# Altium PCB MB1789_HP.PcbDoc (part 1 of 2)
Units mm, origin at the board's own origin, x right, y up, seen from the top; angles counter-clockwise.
Board outline 60 x 34 mm, 4 copper layers (Top Layer, Mid-Layer 1, Mid-Layer 2, Bottom Layer), stack 1.07 mm thick; 66 components, 56 nets, 212 pads, 990 vias.
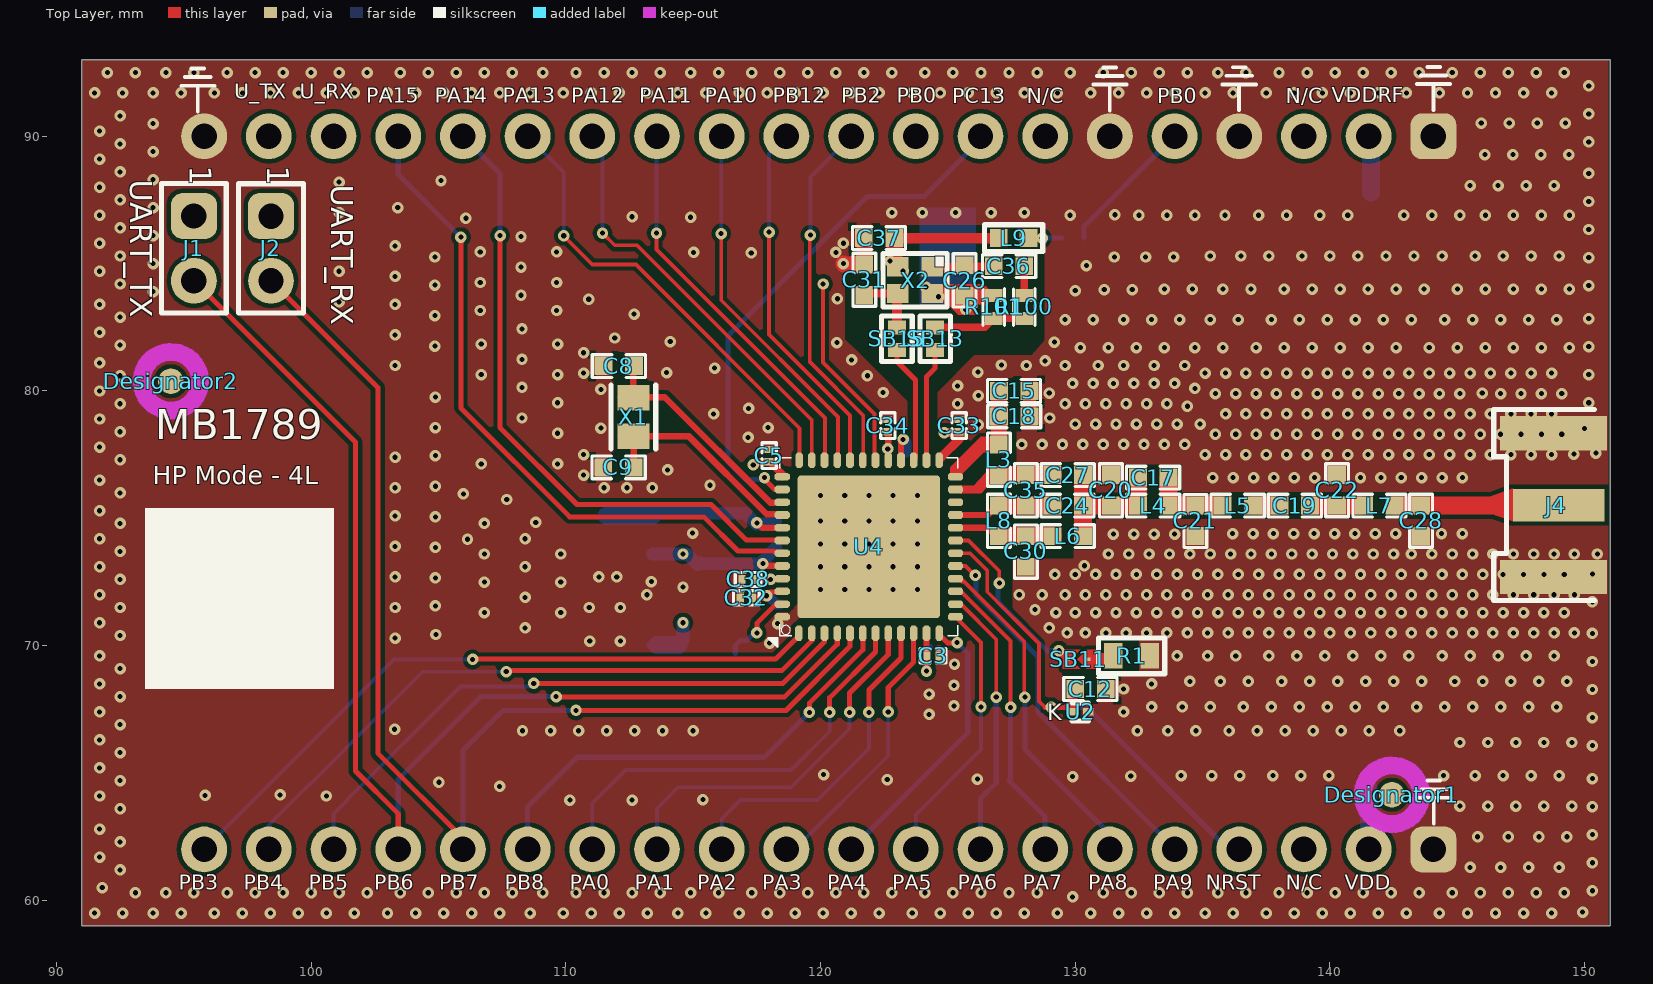
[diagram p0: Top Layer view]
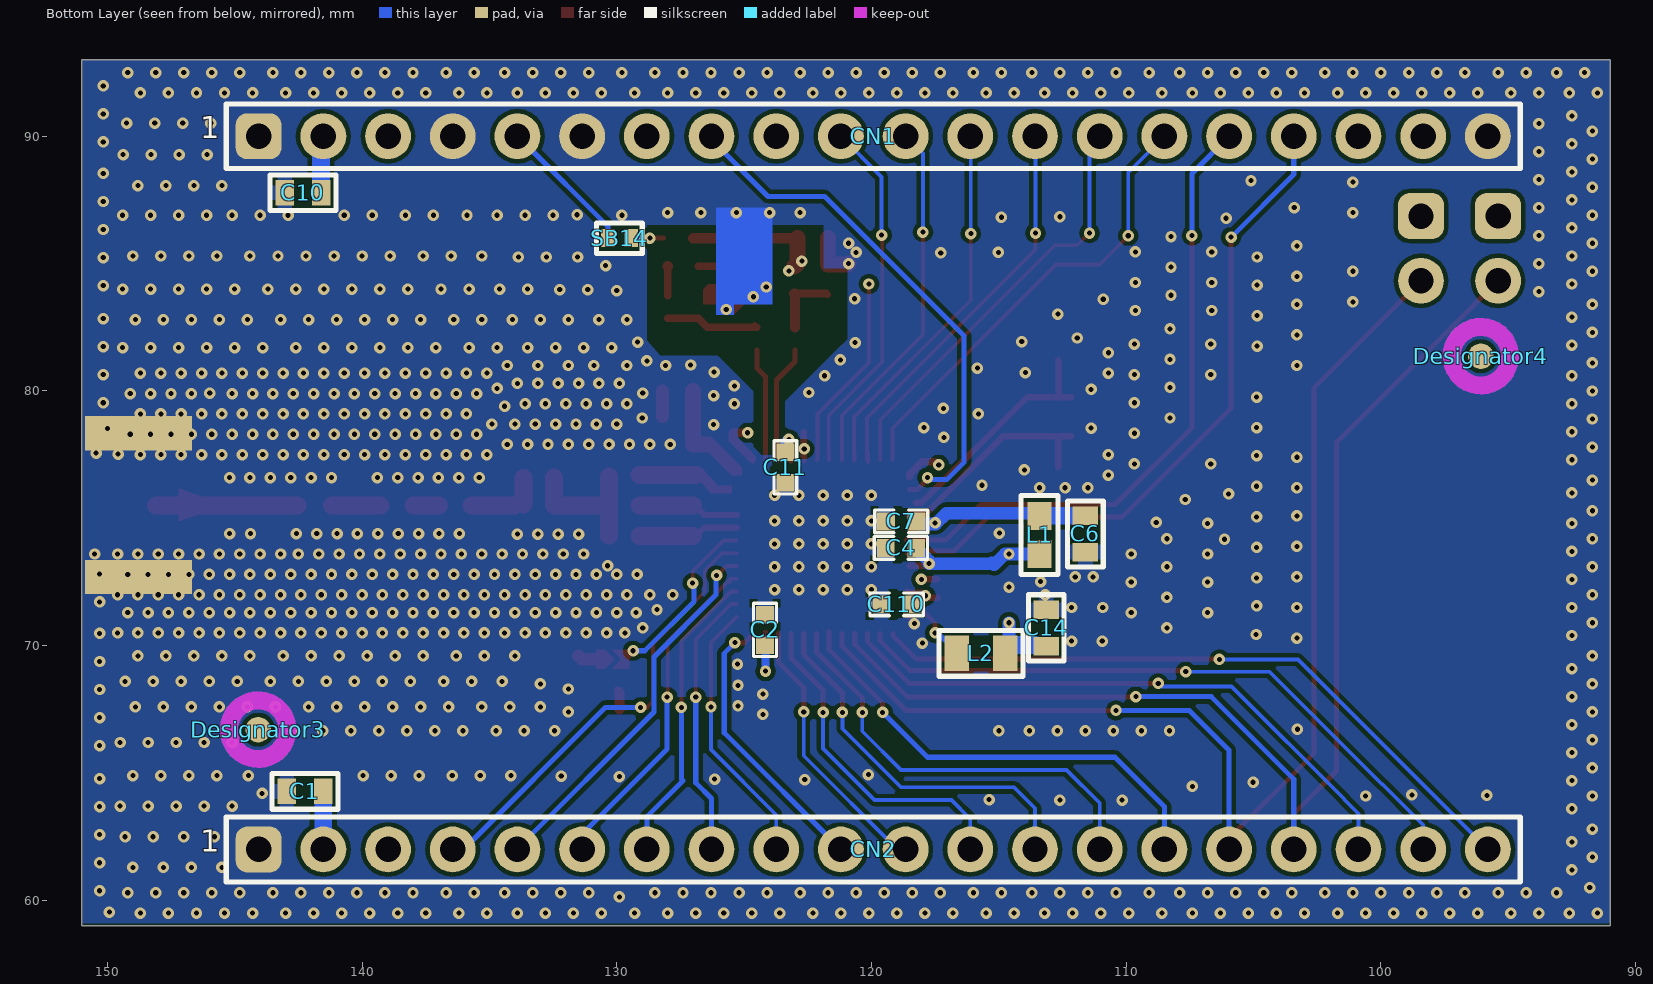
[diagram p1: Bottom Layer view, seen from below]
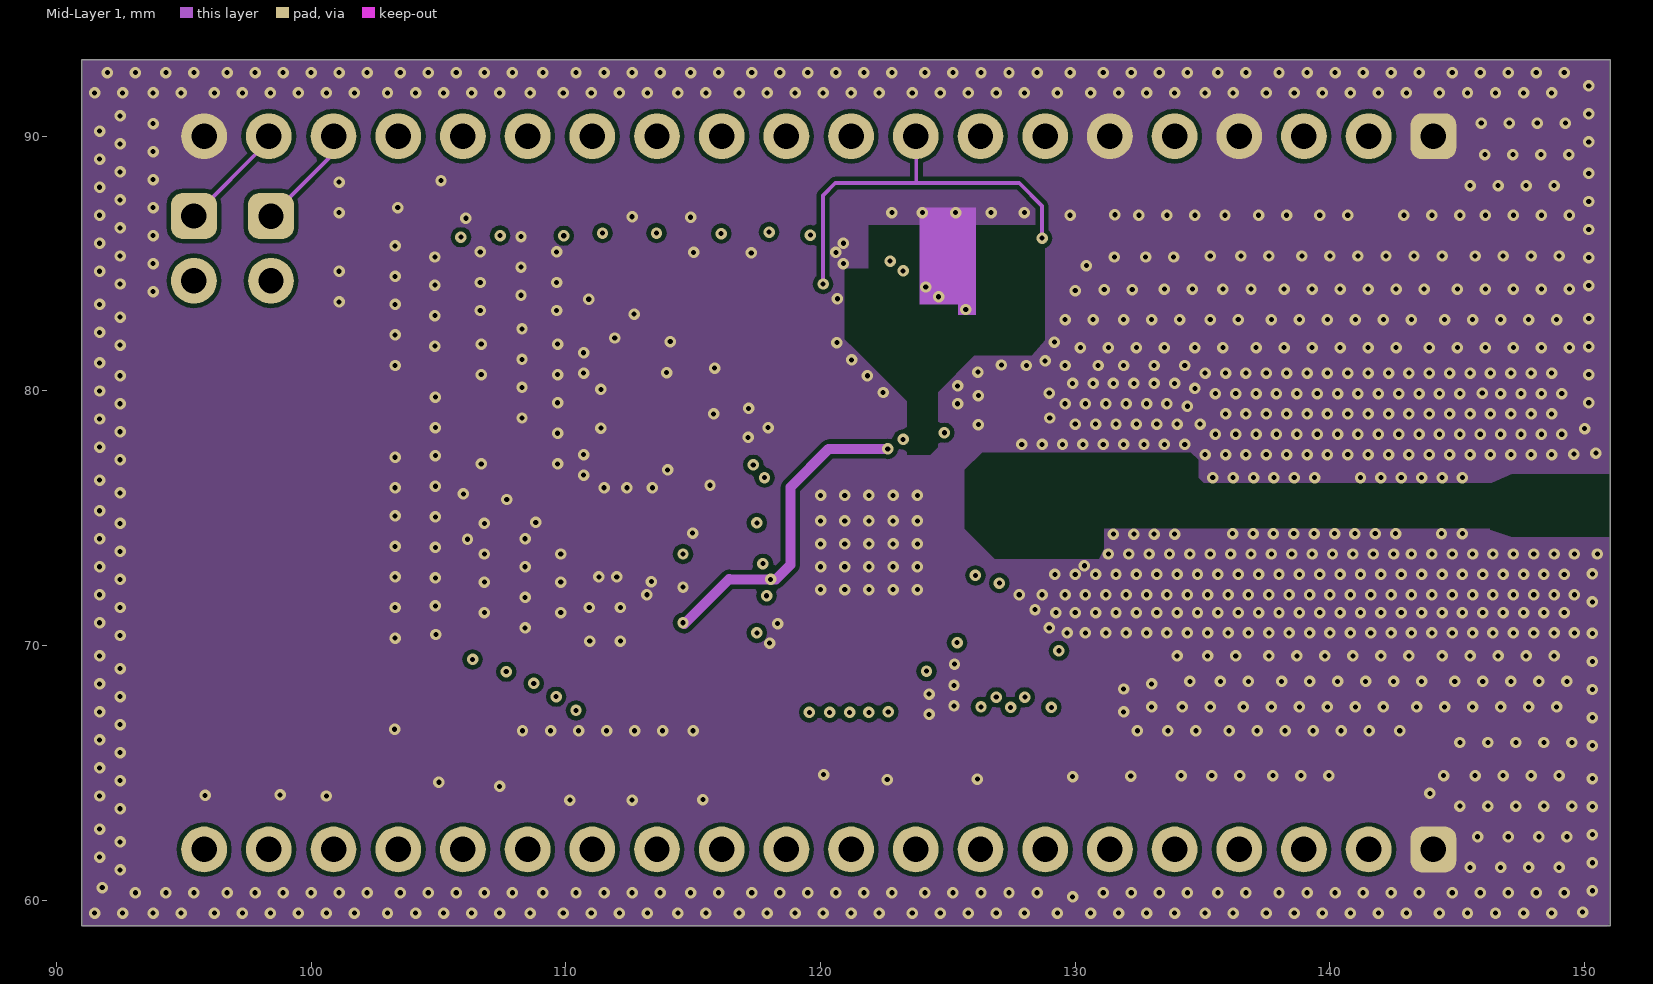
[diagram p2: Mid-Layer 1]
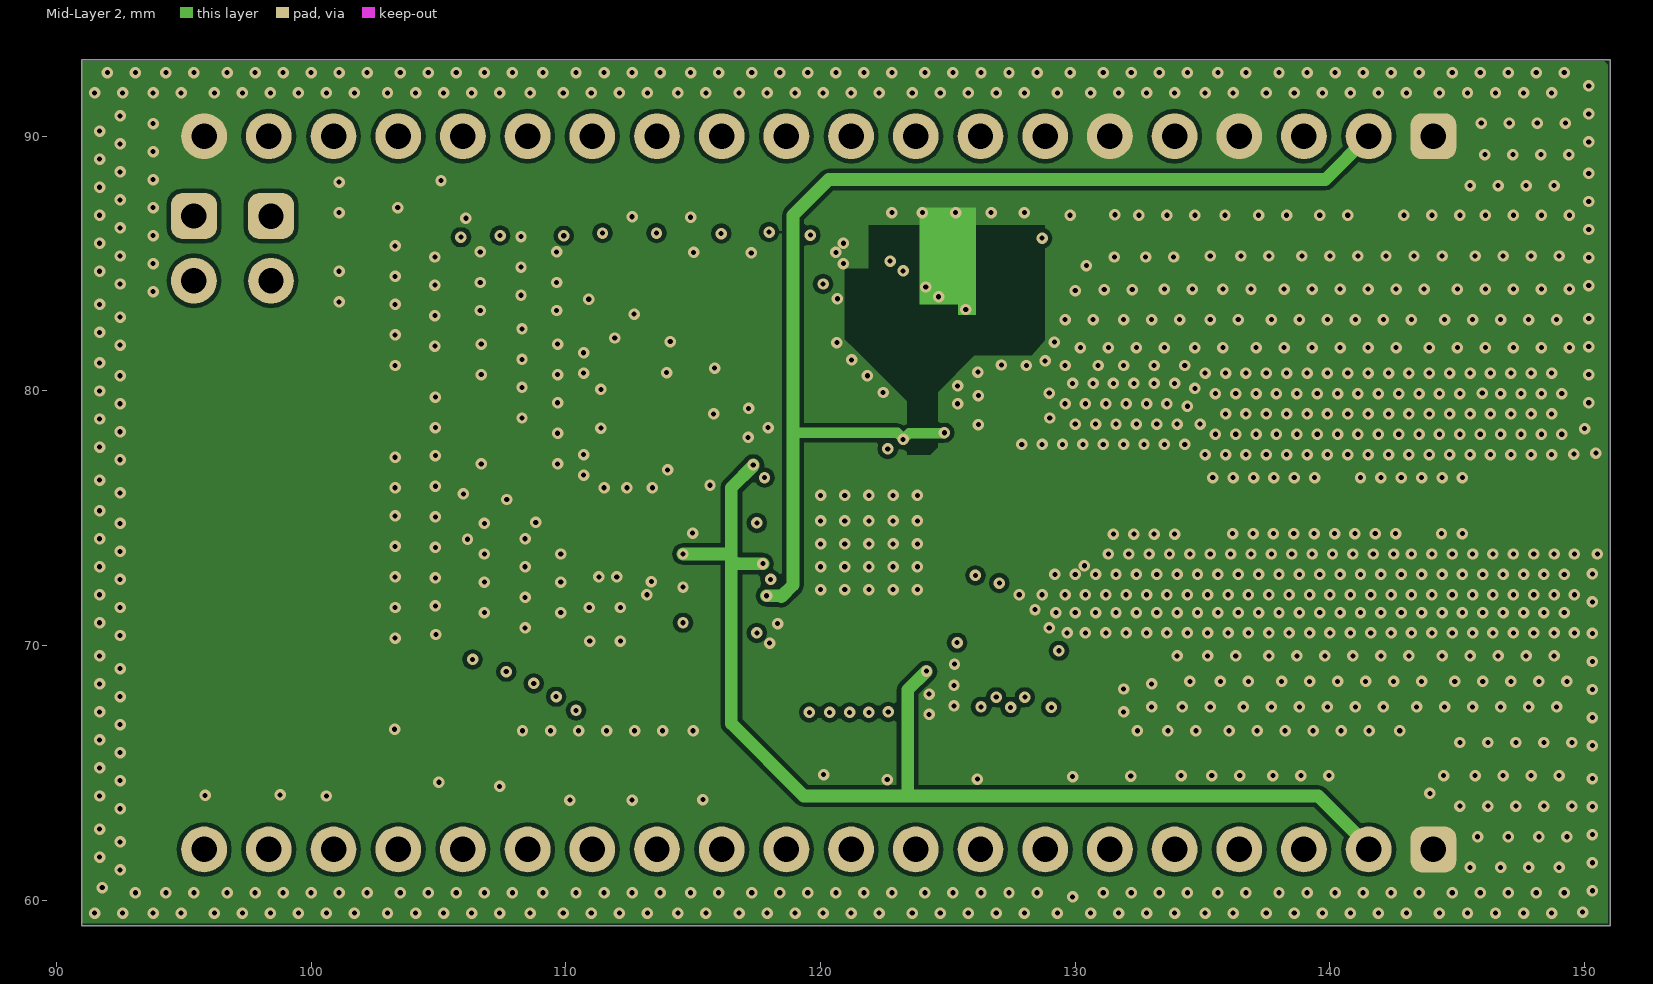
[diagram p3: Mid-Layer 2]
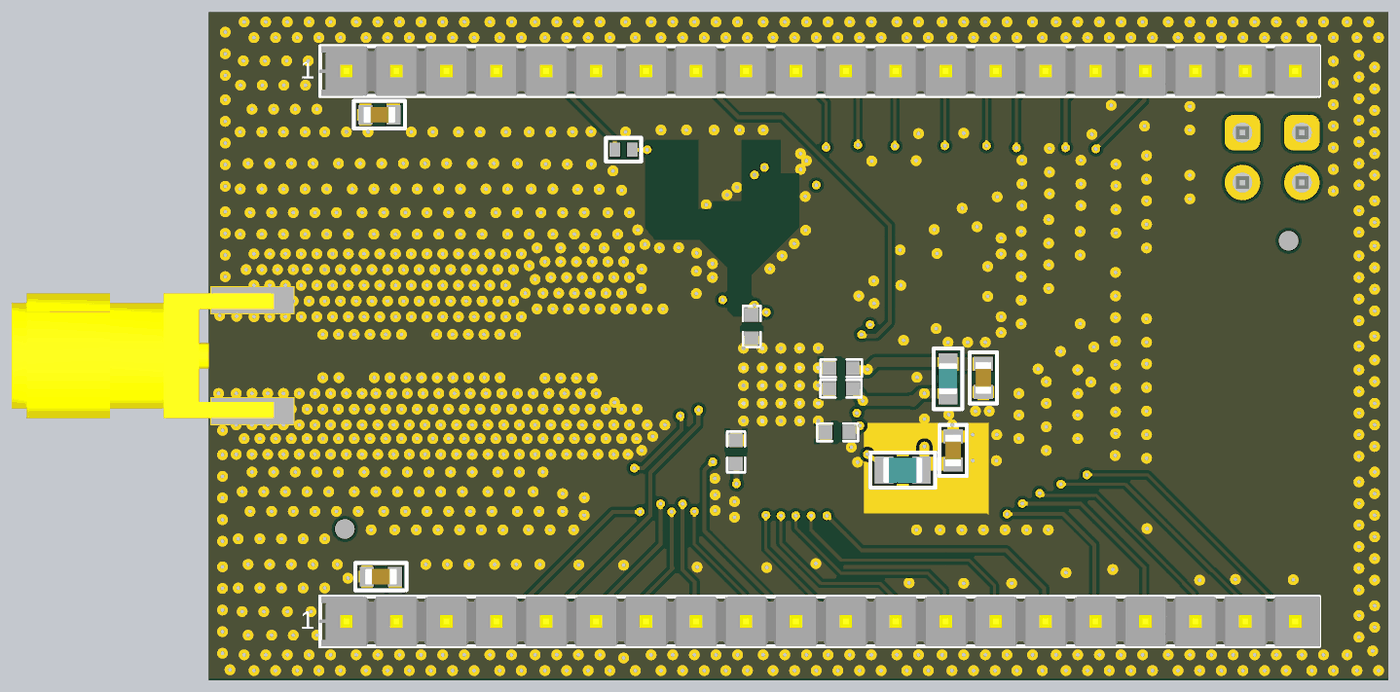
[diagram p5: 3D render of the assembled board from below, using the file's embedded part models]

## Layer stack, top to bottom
Top Solder: solder mask 0.02, Solder Resist, Dk 3.7
Top Layer: signal copper 0.035
Dielectric 1: prepreg 0.16, 1x106 + 1x2116, Dk 3.7
Mid-Layer 1: signal copper 0.035
Dielectric2: dielectric 0.61, FR-4, Dk 5
Mid-Layer 2: signal copper 0.035
Dielectric3: prepreg 0.16, 1x106 + 1x2116, Dk 3.7
Bottom Layer: signal copper 0.035
Bottom Solder: solder mask 0.02, Solder Resist, Dk 3.7

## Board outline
91,59 91,93 151,93 151,59

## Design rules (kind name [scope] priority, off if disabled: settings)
Clearance Clearance_50ohm [InNetClass('50ohm') vs InNamedPolygon('GND_Top')] p1: gap=0.182 ignorepadtopadclearanceinfootprint=FALSE except(0.172: Arc-Fill Arc-Poly Arc-Region Track-Fill Track-Poly Track-Region)
Clearance [All] p2: gap=0.165 ignorepadtopadclearanceinfootprint=FALSE except(0: Arc-Hole Track-Hole SMDPad-Hole THPad-Hole Via-Hole Fill-Hole Poly-Hole Region-Hole Text-Hole)
ComponentClearance [All] p1 off: gap=0.02 collisioncheckmode=3 verticalgap=0.254 showdistances=FALSE
HoleSize [All] p1: absolutevalues=TRUE maxlimit=3.6 minlimit=0.025 maxpercent=80.000 minpercent=20.000
HoleToHoleClearance [All] p1: gap=0.2 allowstackedmicrovias=TRUE
MinimumSolderMaskSliver [All] p1: minsoldermaskwidth=0.001
PolygonConnect PolygonConnect_SMD [InNet('GND') vs HasFootprint('0402')or HasFootprint('CAPC1608X09N')] p1: connectstyle=Relief reliefconductorwidth=0.6 reliefentries=4 polygonreliefangle="90 Angle" airgapwidth=0.254
PolygonConnect [All] p2: connectstyle=Direct reliefconductorwidth=0.254 reliefentries=4 polygonreliefangle="90 Angle" airgapwidth=0.254
RoutingVias [All] p1: holewidth=0.125 width=0.25 viastyle="Through Hole" minholewidth=0.08 minwidth=0.12 maxholewidth=0.5 maxwidth=1
SilkToSilkClearance [All] p1: silktosilkclearance=0.02
SilkToSolderMaskClearance [IsPad] p1 off: minsilkscreentomaskgap=0.02 clearancetoexposedcopper=TRUE
SolderMaskExpansion [All] p1: expansion=0.05 istentingtop=FALSE
Width [All] p1: maxlimit=2 minlimit=0.097 preferedwidth=0.2 minimp=50.000000 maximp=50.000000 favimp=50.000000
24 further rules are at their usual default settings.

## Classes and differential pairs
net class 50ohm: NetC17_1 NetC17_2 NetC19_1 NetC19_2 NetC28_1
component class MB1789_QFN_direct_Tie_HP: C1 C2 C3 C4 C5 C6 C7 C8 C9 C10 C11 C12 C14 C15 C17 C18 C19 C20 C21 C22 C24 C26 C27 C28 C30 C31 C32 C33 C34 C35 C36 C37 C38 C110 CN1 CN2 J1 J2 J4 L1 L2 L3 L4 L5 L6 L7 L8 L9 R1 R100 R101 SB11 SB13 SB14 SB15 U2 U4 X1 X2

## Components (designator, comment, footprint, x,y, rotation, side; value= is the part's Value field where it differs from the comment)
C1 "" CAPC1608X09N 142.24,64.28 r180 bottom value=4.7uF
C2 "" 0402 124.18,71.253 r270 bottom value=100nF
C3 "" 0201 124.66,69.6 r180 top value=33pF
C4 "" 0402 119.473,73.84 r180 bottom value=100nF
C5 "" 0201 117.98,77.7 r270 top value=33pF
C6 "" CAPC1608X09N 111.6,74.387 r270 bottom value=4.7uF
C7 "" 0402 118.2,74.88 r0 bottom value=100nF
C8 "Capacitor" 0402 112.713,80.98 r180 top value=6.8pF
C9 "Capacitor" 0402 112.7,77 r180 top value=6.8pF
C10 "" CAPC1608X09N 142.32,87.78 r0 bottom value=4.7uF
C11 "" 0402 123.38,77.633 r270 bottom value=100nF
C12 "" 0402 129.965,68.3 r0 top value=100nF
C14 "" CAPC1608X09N 113.14,70.7 r90 bottom value="0.47 uF"
C15 "" 0402 126.967,80 r0 top value="47 nF"
C17 "" 0402 132.427,76.6 r0 top
C18 "" 0402 128.235,79 r180 top value="68 pF"
C19 "" 0402 139.253,75.5 r180 top
C20 "" 0402 131.4,75.465 r90 top
C21 "" 0402 134.72,74.267 r90 top
C22 "" 0402 140.28,76.733 r270 top
C24 "" 0402 129.067,75.5 r0 top
C26 "Capacitor" 0402 125.655,84.971 r270 top value=NM
C27 "NC" 0402 130.335,76.7 r180 top
C28 "" 0402 143.58,75.535 r270 top
C30 "" 0402 128.06,73.065 r90 top
C31 "Capacitor" 0402 121.718,83.738 r90 top value=NM
C32 "" 0201 116.85,71.88 r0 top value=33pF
C33 "" 0201 125.44,78.88 r270 top value=33pF
C34 "" 0201 122.64,78.88 r270 top value=33pF
C35 "" 0402 128.06,75.467 r90 top
C36 "" 0402 128.033,84.9 r180 top value=0Ohm
C37 "" 0402 121.665,86 r0 top value="0 Ohm"
C38 "" 0201 117.4,72.6 r180 top value=33pF
C110 "" 0402 118.385,71.62 r0 bottom value=100nF
CN1 "CON20" CO_SAMTEC_TSW-120-07-X-S 119.93,90 r180 bottom
CN2 "CON20" CO_SAMTEC_TSW-120-07-X-S 119.93,62 r180 bottom
Designator1 "MIRE" MIRE 142.431,64.148 r0 top
Designator2 "MIRE" MIRE 94.493,80.382 r0 top
Designator3 "MIRE" MIRE 144.079,66.703 r180 bottom
Designator4 "MIRE" MIRE 96.077,81.366 r180 bottom
Designator5 "Comment" PCB_SPECIFICATIONS 91.034,100.8 r0 top
Designator6 "Comment" Sheetbox_4L2S 91.023,31.471 r0 top
Designator16 "Comment" IMPEDANCE_TABLE 91.067,137.943 r0 top
J1 "HEADER_1X2_L" CO_MOLEX_22-03-2021 95.4,85.6 r270 top
J2 "HEADER_1X2_L" CO_MOLEX_22-03-2021 98.425,85.598 r270 top
J4 "SMA_T_9.52_NF" CO_SAMTEC_SMA-J-P-ST-EMI 150.88,75.52 r90 top
L1 "" INDC1608X95N 113.4,74.35 r90 bottom value=600R@100MHz
L2 "" INDC2012X13N 115.7,69.7 r0 bottom value=15µH
L3 "" 0402 127,77.933 r270 top
L4 "" 0402 132.425,75.5 r0 top
L5 "" 0402 135.746,75.5 r0 top
L6 "" 0402 130.335,74.3 r180 top
L7 "" 0402 142.575,75.5 r180 top
L8 "" 0402 127,75.534 r270 top
L9 "ferrite" IND_MURATA_LQW15A 127.58,86 r0 top value=LQW15AN3N9B00#
R1 "" RESC1608X05N 132.213,69.6 r180 top value=10K
R100 "Resistor" R0402 128,83.3 r90 top value=0
R101 "Resistor" R0402 126.8,83.3 r90 top value=NM
SB11 "Open" GC_0402 130.15,69.469 r180 top
SB13 "Close" SB_0402 124.5,82.05 r90 top value=0
SB14 "Open" SB_0402 129.9,86 r0 bottom
SB15 "Close" SB_0402 123,82.05 r90 top value=0
U2 "" DIOM0603X03N 130.2,67.4 r0 top
U4 "STM32WLxx_QFN48" STM32WLXX_QFN48 121.897,73.883 r90 top
X1 "XTAL_2_PINS" OSC_NDK_NX2012SA 112.655,78.982 r90 top value=32.768KHz
X2 "" OSC_NDK_NX2016SA 123.71,84.353 r180 top value=32MHz

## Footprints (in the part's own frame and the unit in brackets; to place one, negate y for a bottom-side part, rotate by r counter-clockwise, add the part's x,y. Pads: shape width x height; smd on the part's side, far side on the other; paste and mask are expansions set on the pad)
0201 [mm]
  rect 0.28x0.35 smd: 1(0,0) 2(0.48,0)
  silkscreen extent -0.27,-0.28 0.75,0.28, body extent -0.06,-0.15 0.54,0.15, height 0.3
0402 [mm]
  rect 0.7x0.7 smd: 1(0.035,0) 2(1.233,0)
  silkscreen extent -0.41,-0.45 1.67,0.45, body extent -0.38,-0.36 1.65,0.36, height 0.82
CAPC1608X09N [mm] "Chip Capacitor, 2-Leads, Body 1.60x0.80x0.90mm (0603)"
  rect 0.725x1 smd: 1(-0.713,0) 2(0.713,0)
  Top Layer pour cut-out: -0.3,0.7 0.3,0.7 0.3,-0.7 -0.3,-0.7
  silkscreen extent -1.3,-0.7 1.3,0.7, body extent -0.8,-0.4 0.8,0.4, height 0.9
CO_MOLEX_22-03-2021 [mm]
  rrect50% 1.8x1.8 hole 1: 1(-1.27,0)
  round 1.8 hole 1: 2(1.27,0)
  silkscreen extent -2.54,-1.27 2.54,1.27, body extent -2.41,-1.18 2.41,1.18, height 10.79
CO_SAMTEC_SMA-J-P-ST-EMI [mm] "SMA Jack CMS, Edge Mountt Receptacle 50Ohm, 5-Leads, Body 6.35x6.35x9.52mm, pitch 2.825mm"
  rect 1.27x3.6 smd mask+0.05: 1(0,1.9)
  rect 1.35x4.2 smd mask+0.05: 2(-2.825,2.1) 2(2.825,2.1)
  rect 1.35x4.2 smd far side mask+0.05: 2(-2.825,2.1) 2(2.825,2.1)
  silkscreen extent -3.75,0.5 3.75,4.45, body extent -3.17,-10.13 3.17,3.2, height 3.8
CO_SAMTEC_TSW-120-07-X-S [mm] "Header, 20-Leads, 50.80x2.54x10.80mm, Pitch 2.54mm"
  rrect50% 1.8x1.8 hole 1: 1(-24.13,0)
  round 1.8 hole 1: 2(-21.59,0) 3(-19.05,0) 4(-16.51,0) 5(-13.97,0) 6(-11.43,0) 7(-8.89,0) 8(-6.35,0) 9(-3.81,0) 10(-1.27,0) 11(1.27,0) 12(3.81,0) 13(6.35,0) 14(8.89,0) 15(11.43,0) 16(13.97,0) 17(16.51,0) 18(19.05,0) 19(21.59,0) 20(24.13,0)
  silkscreen extent -25.4,-1.27 25.4,1.27, body extent -25.46,-1.27 25.46,1.27, height 8.38
DIOM0603X03N [mm] "Molded Diode, 2-Leads, Body 0.60x0.30mm"
  rect 0.425x0.3 smd: 1(-0.312,0) 2(0.313,0)
  silkscreen extent -0.33,-0.35 0.33,0.35, body extent -0.32,-0.18 0.33,0.18, height 0.33
GC_0402 [mm] "Grain de café format 0402"
  rect 0.15x0.15 smd paste-1: 1(-0.375,0) 2(0.45,0)
  Top Layer region: -0.65,0.375 -0.3,0.375 0.075,0 -0.3,-0.375 -0.65,-0.375
  Top Layer region: -0.05,0.375 0.65,0.375 0.65,-0.375 -0.05,-0.375 0.325,0
  body extent -0.5,-0.25 0.6,0.25, height 0.2
IMPEDANCE_TABLE [mm]
IND_MURATA_LQW15A [mm] "Inductor 2-Leads,Body 1.10x0.70x0.60mm(max)"
  rect 0.7x0.7 smd: 1(-0.58,0) 2(0.58,0)
  silkscreen extent -1.14,-0.53 1.14,0.53, body extent -0.5,-0.3 0.5,0.3, height 0.51
INDC1608X95N [mm] "Chip Inductor, 2-Leads, Body 1.75x0.95x0.95mm (0603)"
  rect 1.1x0.95 smd: 1(-0.75,0) 2(0.75,0)
  silkscreen extent -1.55,-0.72 1.55,0.72, body extent -0.8,-0.48 0.8,0.47, height 0.8
INDC2012X13N [mm] "Chip Inductor, 2-Leads, Body 2.0x1.2x1.3 (0805)"
  rect 0.96x1.4 smd: 1(-0.953,0) 2(0.953,0)
  silkscreen extent -1.65,-0.9 1.65,0.9, body extent -1,-0.65 1,0.65, height 1.18
MIRE [mm] "Fiducial Target Round , Pad 1.0mm, Keepout 3mm"
  round 1 smd: 1(0,0)
  Top Layer keep-out circle w0.7: c0,0 r1.15
  body extent -0.5,-0.5 0.5,0.5, height 0.04
OSC_NDK_NX2012SA [mm] "Crystal, 2-Leads, Body 2.05x1.20x0.55mm (Tol:-/+0.05)"
  rect 1x1.25 smd: 1(-0.75,0) 2(0.75,0)
  silkscreen extent -1.25,-0.87 1.25,0.87, body extent -1.04,-0.63 1.03,0.63, height 0.55
OSC_NDK_NX2016SA [mm] "Crystal, 4-Leads, Body 2.10x1.61x0.50mm (max), Pitch 1.35x1.05mm"
  rect 0.85x0.75 smd: 1(-0.675,-0.525) 2(0.675,-0.525) 3(0.675,0.525) 4(-0.675,0.525)
  silkscreen extent -1.25,-1.05 1.25,1.05, body extent -1,-0.8 1,0.8, height 0.5
PCB_SPECIFICATIONS [mm]
R0402 [mm]
  rect 0.51x0.7 smd mask+0.05: 1(-0.45,0) 2(0.45,0)
  silkscreen extent -0.72,-0.43 0.72,0.43, body extent -0.52,-0.3 0.52,0.3, height 0.4
RESC1608X05N [mm] "Chip Resistor, 2-Leads, Body 1.60x0.80mm (0603)"
  rect 0.725x1 smd: 1(-0.713,0) 2(0.713,0)
  Top Layer pour cut-out: -0.3,0.7 0.3,0.7 0.3,-0.7 -0.3,-0.7
  silkscreen extent -1.3,-0.7 1.3,0.7, body extent -0.77,-0.42 0.78,0.43, height 0.45
SB_0402 [mm] "Solder Bridge 0 Ohm (0402)"
  rect 0.55x0.7 smd: 1(-0.45,0) 2(0.45,0)
  silkscreen extent -0.9,-0.6 0.9,0.6, body extent -0.5,-0.25 0.5,0.25, height 0.25
Sheetbox_4L2S [mil] "Sheetbox 4 layers / 2 silkscreens"
  round 20 on Mech16: 1(813.78,210.69) 1(2736.9,210.69)
STM32WLXX_QFN48 [mm] "QFN48 7x7x0.55mm pitch 0.5mm"
  oct 0.6x0.3 smd mask+0.06: 1(-3.398,2.746) 2(-3.398,2.239) 3(-3.398,1.739) 4(-3.398,1.239) 5(-3.398,0.739) 6(-3.398,0.239) 7(-3.398,-0.261) 8(-3.398,-0.761) 9(-3.398,-1.261) 10(-3.398,-1.761) 11(-3.398,-2.261) 12(-3.398,-2.761) 25(3.398,-2.761) 26(3.398,-2.261) 27(3.398,-1.761) 28(3.398,-1.261) 29(3.398,-0.761) 30(3.398,-0.261) 31(3.398,0.239) 32(3.398,0.739) 33(3.398,1.239) 34(3.398,1.739) 35(3.398,2.239) 36(3.398,2.739)
  oct 0.3x0.6 smd mask+0.06: 13(-2.752,-3.399) 14(-2.252,-3.399) 15(-1.752,-3.399) 16(-1.252,-3.399) 17(-0.752,-3.399) 18(-0.252,-3.399) 19(0.248,-3.399) 20(0.748,-3.399) 21(1.248,-3.399) 22(1.748,-3.399) 23(2.248,-3.399) 24(2.748,-3.399) 37(2.748,3.399) 38(2.248,3.399) 39(1.748,3.399) 40(1.248,3.399) 41(0.748,3.399) 42(0.248,3.399) 43(-0.252,3.399) 44(-0.752,3.399) 45(-1.252,3.399) 46(-1.752,3.399) 47(-2.252,3.399) 48(-2.752,3.399)
  rrect5% 5.6x5.6 smd paste-3 mask+0.08: 49(0,0)
  silkscreen extent -3.95,-3.5 3.5,3.96, body extent -3.51,-3.51 3.51,3.51, height 0.78

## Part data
C1 C6 C10: library part MCD-00009, "Capacitor, MLCC, 4.7uF, 16V, X5R, 10%, 0603, T=0.8mm", Manufacturer=YAGEO, Manufacturer_Part_Number=CC0603KRX5R7BB475, Package=C0603
C2 C3 C4 C5 C7 C11 C12 C110: library part MCD-00102, "Capacitor, MLCC, 100nF, 16V, X7R, 10%, 0402, T=0,5mm", Manufacturer=YAGEO, Manufacturer_Part_Number=CC0402KRX7R7BB104, Package=C0402
C8 C9 C26 C31: library part MCD-00003, "Capacitor, MLCC, 6.8pF, 50V, NPO, +-0.1pF, 0402, T=0.5mm", Manufacturer=MURATA, Manufacturer_Part_Number=GRM1555C1H6R8BA01
C14: library part MCD-00009, "Capacitor, MLCC, 4.7 uF, 16V, X5R, 10%, 0603, T=0.8mm", Manufacturer=YAGEO, Manufacturer_Part_Number=CC0603KRX5R7BB474, Package=C0603
C15: library part MCD-01123, "Capacitor, MLCC,47nF, 16V, X7R, 10%, 0402, T=0.5mm", Manufacturer=MURATA, Manufacturer_Part_Number=GCM155R71E473KA55
C17: library part MCD-01123
C18 C38: library part MCD-01123, "Capacitor, MLCC,68pF, 50V, C0G, 1%, 0402, T=0.5mm", Manufacturer=MURATA, Manufacturer_Part_Number=GCM1555C1H680JA16
C19: library part MCD-01123, "Condensateurs céramique multicouches MLCC - CMS 33PF 50V 2% 0402"
C20: library part MCD-00102, "N/C", Manufacturer=Murata, Manufacturer_Part_Number="Not Connected", Package=C0402
C21: library part MCD-00015, "Condensateurs céramique multicouches MLCC - CMS 0402 3.3pF 50Volts C0G +/-0.05pF"
C22: library part MCD-01123, "Condensateurs céramique multicouches MLCC - CMS 0402 2.7 pF 50Volts C0G +/-0.25pF"
C24: library part MCD-01123, "Condensateurs céramique multicouches MLCC - CMS 0402 3.6pF 50Volts C0G +/-0.05pF", Manufacturer=MURATA, Manufacturer_Part_Number=GJM1555C1H3R6WB01D
C27: library part MCD-01123, "Not connected [0402]", Manufacturer=MURATA
C28: library part Capacitor, "Condensateurs céramique multicouches MLCC - CMS 0402 3.3pF 50Volts C0G +/-0.05pF", Package=C0402
C30 C35: library part MCD-01123, "Condensateurs céramique multicouches MLCC - CMS 0402 2.7pF 50Volts C0G +/-0.1pF", Manufacturer=MURATA, Manufacturer_Part_Number=GJM1555C1H2R7BB01D
C32 C33 C34 C36 C37: library part MCD-00277, "Capacitor, MLCC, 33pF, 50V, NPO, 2%, 0402, T=0,5mm", Manufacturer=MURATA, Manufacturer_Part_Number=GRM1555C1H330GA01
CN1 CN2: "Connector"
Designator16: library part MCD-00279
J4: "SMA Jack, Edge Mount, 50 Ohms", Manufacturer=SAMTEC, Manufacturer_Part_Number=SMA-J-P-H-ST-EM1
L1: library part MCD-00047, "SMD Chip ferrite bead, 600R@100MHz +/-25%, 350mA, 500mohm DC, 0603, T=0.8mm", Manufacturer=TAI-TECH, Manufacturer_Part_Number=FCM1608KF-601T03
L2: library part MCD-01433, "MLZ2012 Multilayer Shielded Inductor 15µH, ±5%", Manufacturer=TDK, Manufacturer_Part_Number=MLZ2012M150W
L3: library part MCD-01330, "Inductor, 68nH, +-0.1nH, 140mA, 0402"
L4: library part MCD-01330, "Inductor, 8.2nH, +-0.2nH, 750mA, 0402"
L5: library part MCD-01330, "Inductor, 8.7nH, +-0.1nH, 540mA, 0402"
L6: library part MCD-01330, "Résistance 0 ohm", Manufacturer="Vishay / Dale", Manufacturer_Part_Number=RCS04020000Z0ED
L7: library part MCD-01330, "Inductor, 15nH, +-0.1nH, 640mA, 0402"
L8: library part MCD-01330, "Inductor, 11 nH, +-0.1nH, 270mA, 0402", Manufacturer=MURATA, Manufacturer_Part_Number=LQW15AN11NG00D
L9: library part MCD-01330, "Inductor, 3.9nH, +-0.1nH, 750mA, 0402", Manufacturer=MURATA, Manufacturer_Part_Number=LQW15AN3N9B00#, Package=L0402
R1: library part MCD-00220, "Resistor,10K,0603,1%,1/10W", Manufacturer=YAGEO, Manufacturer_Part_Number=RC0603FR-0710KL
R100 R101: library part MCD-00052, "Resistor,0R,0402,5%,1/16W", Manufacturer=YAGEO, Manufacturer_Part_Number=RC0402JR-070RL, Package=R0402
SB11: library part Strap2, "Solder Jumper - Close"
SB13 SB15: library part SB_0Ohm, "Solder Bridge 0R [0402] (Populated with 0 Ohm)", Manufacturer="Vishay / Dale", Manufacturer_Part_Number=RCS04020000Z0ED
SB14: library part SB_Open, "Solder Bridge Open [0402] (Unpopulated)"
U2: library part MCD-00170, "ESD protection 6V1", Manufacturer=STMICROELECTRONICS, Manufacturer_Part_Number=ESDALC6V1-1U2
U4: "HQDC : Verified April, 25 2019"
X1: library part MCD-01479, "Crystal 32.768kHz, 6pF, -+20PPM, R=80K, SMD", Manufacturer=NDK, Manufacturer_Part_Number="NX2012SA 32.768KHz EXS00A-MU00527"
X2: library part MCD-01446, "Crystal 32 MHz, 8pF, -+10 PPM, R=60O, SMD", Manufacturer=NDK, Manufacturer_Part_Number="NX2016SA 32MHz EXS00A-CS06465"

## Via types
v1: diameter 0.45, hole 0.2, Top Layer to Bottom Layer, 990 vias

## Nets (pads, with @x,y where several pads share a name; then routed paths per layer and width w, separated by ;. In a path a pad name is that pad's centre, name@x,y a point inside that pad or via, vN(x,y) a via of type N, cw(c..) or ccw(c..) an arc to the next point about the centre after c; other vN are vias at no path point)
GND: C1.1 C2.1 C3.1 C4.1 C5.1 C6.2 C7.2 C8.2 C9.2 C10.2 C11.2 C12.2 C14.2 C15.2 C18.1 C20.2 C21.1 C22.1 C26.2 C28.2 C30.1 C31.2 C32.1 C33.1 C34.1 C37.1 C38.2 C110.2 CN1.1 CN1.4 CN1.6 CN1.20 CN2.1 J4.2 R1.1 R101.2 U2.2 U4.48 U4.49 X2.4 | length 3.4
  Top Layer w0.2: v1(118.316,70.866) 118.316,70.878 U4.48@118.6,71.162
  Top Layer w0.5: C18.1@128.2,79 C15.2@128.2,80
  Top Layer w0.625: v1(120.9,85) 120.929,84.971 C31.2@121.718,84.971 121.718,85.982 C37.1@121.7,86 ; C26.2@125.565,83.828 C26.2@125.655,83.738
  other v1: 91.5,59.5 92.6,59.5 93.8,59.5 94.9,59.5 96.2,59.5 97.3,59.5 98.4,59.5 99.5,59.5 100.6,59.5 101.7,59.5 103,59.5 104.1,59.5 105.2,59.5 106.3,59.5 107.4,59.5 108.6,59.5 109.9,59.5 111,59.5 112.1,59.5 113.2,59.5 114.4,59.5 115.5,59.5 116.8,59.5 117.9,59.5 119,59.5 120.1,59.5 121.2,59.5 122.3,59.5 123.6,59.5 124.7,59.5 125.8,59.5 126.9,59.5 128,59.5 129.3,59.5 130.6,59.5 131.7,59.5 132.8,59.5 133.9,59.5 135.1,59.5 136.2,59.5 137.5,59.5 138.6,59.5 139.7,59.5 140.8,59.5 141.9,59.5 143,59.5 144.3,59.5 145.4,59.5 146.5,59.5 147.6,59.5 148.7,59.5 149.92,59.54 129.9,60.14 93.1,60.3 94.3,60.3 95.4,60.3 96.7,60.3 97.8,60.3 98.9,60.3 100,60.3 101.1,60.3 102.2,60.3 103.5,60.3 104.6,60.3 105.7,60.3 106.8,60.3 107.9,60.3 109.1,60.3 110.4,60.3 111.5,60.3 112.6,60.3 113.7,60.3 114.9,60.3 116,60.3 117.3,60.3 118.4,60.3 119.5,60.3 120.6,60.3 121.7,60.3 122.8,60.3 124.1,60.3 125.2,60.3 126.3,60.3 127.4,60.3 128.5,60.3 131.1,60.3 132.2,60.3 133.3,60.3 134.4,60.3 135.6,60.3 136.7,60.3 138,60.3 139.1,60.3 140.2,60.3 141.3,60.3 142.4,60.3 143.5,60.3 144.8,60.3 145.9,60.3 147,60.3 148.1,60.3 149.2,60.3 150.3,60.38 91.8,60.5 92.5,61.2 145.5,61.3 146.7,61.3 147.8,61.3 149,61.3 150.3,61.48 91.7,61.7 92.5,62.3 145.8,62.5 147,62.5 148.2,62.5 149.3,62.5 150.3,62.58 91.7,62.8 92.5,63.6 150.3,63.68 145.1,63.7 146.2,63.7 147.3,63.7 148.4,63.7 149.5,63.7 110.16,63.94 112.6,63.94 115.38,63.96 91.7,64.1 95.84,64.12 100.6,64.1 98.78,64.14 143.92,64.2 107.4,64.48 105.02,64.64 92.5,64.7 122.62,64.74 126.16,64.76 150.3,64.78 129.9,64.86 132.18,64.88 134.16,64.9 135.36,64.9 136.46,64.9 137.76,64.9 138.86,64.9 139.96,64.9 144.46,64.9 145.7,64.9 146.8,64.9 147.9,64.9 149,64.9 120.12,64.94 91.7,65.2 92.5,65.8 150.3,66.08 145.1,66.2 146.2,66.2 147.3,66.2 148.4,66.2 149.5,66.2 91.7,66.3 108.3,66.66 109.4,66.66 110.5,66.66 111.6,66.66 112.7,66.66 113.8,66.66 115,66.66 132.44,66.66 133.64,66.66 134.74,66.66 136.04,66.66 137.14,66.66 138.24,66.66 139.34,66.66 140.44,66.66 141.54,66.66 142.74,66.66 103.28,66.72 92.5,66.9 150.3,67.18 124.26,67.3 91.7,67.4 131.9,67.4 133,67.6 134.2,67.6 135.3,67.6 136.6,67.6 137.7,67.6 138.8,67.6 139.9,67.6 141,67.6 142.1,67.6 143.4,67.6 144.5,67.6 145.6,67.6 146.7,67.6 147.8,67.6 148.9,67.6 125.24,67.64 92.5,68 124.26,68.1 150.3,68.28 131.9,68.3 125.24,68.44 91.7,68.5 133,68.5 134.5,68.6 135.7,68.6 136.8,68.6 138.1,68.6 139.2,68.6 140.3,68.6 141.4,68.6 142.5,68.6 143.6,68.6 144.9,68.6 146,68.6 147.1,68.6 148.2,68.6 149.3,68.6 92.5,69.1 125.26,69.28 150.3,69.38 91.7,69.6 134,69.6 135.2,69.6 136.3,69.6 137.6,69.6 138.7,69.6 139.8,69.6 140.9,69.6 142,69.6 143.1,69.6 144.4,69.6 145.5,69.6 146.6,69.6 147.7,69.6 148.8,69.6 118,70.1 110.94,70.18 112.14,70.18 103.3,70.3 92.5,70.4 104.9,70.44 150.3,70.48 129.68,70.5 130.4,70.5 131.2,70.5 132,70.5 132.8,70.5 133.6,70.5 134.4,70.5 135.2,70.5 136,70.5 136.8,70.5 137.6,70.5 138.4,70.5 139.2,70.5 140,70.5 140.8,70.5 141.6,70.5 142.4,70.5 143.2,70.5 144,70.5 144.8,70.5 145.6,70.5 146.4,70.5 147.2,70.5 148,70.5 148.8,70.5 149.6,70.5 108.4,70.7 128.98,70.7 91.7,70.9 106.8,71.3 109.8,71.3 129.24,71.3 130,71.3 130.8,71.3 131.6,71.3 132.4,71.3 133.2,71.3 134,71.3 134.8,71.3 135.6,71.3 136.4,71.3 137.2,71.3 138,71.3 138.8,71.3 139.6,71.3 140.4,71.3 141.2,71.3 142,71.3 142.8,71.3 143.6,71.3 144.4,71.3 145.2,71.3 146,71.3 146.8,71.3 147.6,71.3 148.4,71.3 149.2,71.3 128.42,71.42 92.5,71.5 103.3,71.5 110.92,71.5 112.14,71.5 104.88,71.56 150.3,71.72 108.4,71.9 91.7,72 113.18,72 127.8,72 128.7,72 129.6,72 130.4,72 131.2,72 132,72 132.8,72 133.6,72 134.4,72 135.2,72 136,72 136.8,72 137.6,72 138.4,72 139.2,72 140,72 140.8,72 141.6,72 142.4,72 143.2,72 144,72 144.8,72 145.6,72 146.4,72 147.2,72 148,72 148.8,72 149.6,72 120,72.2 120.95,72.2 121.9,72.2 122.85,72.2 123.8,72.2 114.6,72.3 106.8,72.5 109.8,72.5 113.363,72.517 92.5,72.6 104.88,72.66 103.3,72.7 111.3,72.7 112,72.7 129.2,72.8 130,72.8 130.8,72.8 131.6,72.8 132.4,72.8 133.2,72.8 134,72.8 134.8,72.8 135.6,72.8 136.4,72.8 137.2,72.8 138,72.8 138.8,72.8 139.6,72.8 140.4,72.8 141.2,72.8 142,72.8 142.8,72.8 143.6,72.8 144.4,72.8 145.2,72.8 146,72.8 146.8,72.8 147.6,72.8 148.4,72.8 149.2,72.8 150.3,72.82 91.7,73.1 108.4,73.1 120,73.1 120.95,73.1 121.9,73.1 122.85,73.1 123.8,73.1 130.36,73.14 106.8,73.6 109.8,73.6 131.3,73.6 132.1,73.6 132.9,73.6 133.7,73.6 134.5,73.6 135.3,73.6 136.1,73.6 136.9,73.6 137.7,73.6 138.5,73.6 139.3,73.6 140.1,73.6 140.9,73.6 141.7,73.6 142.5,73.6 143.2,73.6 144,73.6 144.8,73.6 145.6,73.6 146.4,73.6 147.2,73.6 148,73.6 148.8,73.6 149.6,73.6 150.5,73.6 92.5,73.7 104.88,73.86 103.3,73.9 120,74 120.95,74 121.9,74 122.85,74 123.8,74 106.14,74.18 91.7,74.2 108.4,74.2 131.5,74.38 132.3,74.38 133.1,74.38 133.9,74.38 136.18,74.4 136.98,74.4 137.78,74.4 138.58,74.4 139.38,74.4 140.18,74.4 140.98,74.4 141.78,74.4 142.58,74.4 144.38,74.4 145.2,74.4 114.98,74.42 92.5,74.8 106.8,74.8 108.82,74.84 120,74.9 120.95,74.9 121.9,74.9 122.85,74.9 123.8,74.9 104.88,75.06 103.3,75.1 91.7,75.3 107.68,75.74 120,75.9 120.95,75.9 121.9,75.9 122.85,75.9 123.8,75.9 105.98,75.96 92.5,76 103.3,76.2 111.5,76.2 112.4,76.2 113.4,76.2 104.88,76.26 115.66,76.3 91.7,76.5 135.4,76.6 136.2,76.6 137,76.6 137.8,76.6 138.6,76.6 139.4,76.6 141.2,76.6 142,76.6 142.8,76.6 143.6,76.6 144.4,76.6 145.2,76.6 110.7,76.7 114,76.9 106.68,77.14 109.68,77.14 92.5,77.3 103.3,77.4 104.88,77.46 110.7,77.5 135.1,77.5 135.9,77.5 136.7,77.5 137.5,77.5 138.3,77.5 139.1,77.5 139.9,77.5 140.7,77.5 141.5,77.5 142.3,77.5 143.1,77.5 143.9,77.5 144.7,77.5 145.5,77.5 146.3,77.5 147.1,77.5 147.9,77.5 148.7,77.5 149.58,77.52 150.44,77.56 91.7,77.8 127.9,77.9 128.7,77.9 129.5,77.9 130.3,77.9 131.1,77.9 131.9,77.9 132.7,77.9 133.5,77.9 134.3,77.9 117.16,78.18 135.5,78.3 136.3,78.3 137.1,78.3 137.9,78.3 138.7,78.3 139.5,78.3 140.3,78.3 141.1,78.3 141.9,78.3 142.7,78.3 143.5,78.3 144.3,78.3 145.1,78.3 145.9,78.3 146.7,78.3 147.5,78.3 148.3,78.3 149.1,78.3 109.68,78.34 92.5,78.4 150,78.52 111.38,78.54 104.88,78.56 117.94,78.56 126.2,78.68 130,78.7 130.8,78.7 131.6,78.7 132.4,78.7 133.2,78.7 134,78.7 134.9,78.7 91.7,78.9 108.28,78.94 129,78.94 115.8,79.1 135.9,79.1 136.7,79.1 137.5,79.1 138.3,79.1 139.1,79.1 139.9,79.1 140.7,79.1 141.5,79.1 142.3,79.1 143.1,79.1 143.9,79.1 144.7,79.1 145.5,79.1 146.3,79.1 147.1,79.1 147.9,79.1 148.7,79.1 117.18,79.32 134.4,79.4 92.5,79.5 125.38,79.5 129.6,79.5 130.4,79.5 131.2,79.5 132,79.5 132.8,79.5 133.6,79.5 109.68,79.54 150.16,79.54 104.88,79.76 126.2,79.82 128.98,79.92 135.5,79.9 136.3,79.9 137.1,79.9 137.9,79.9 138.7,79.9 139.5,79.9 140.3,79.9 141.1,79.9 141.9,79.9 142.7,79.9 143.5,79.9 144.3,79.9 145.1,79.9 145.98,79.92 146.7,79.9 147.5,79.9 148.3,79.9 149.1,79.9 122.46,79.94 91.7,80 111.38,80.06 134.7,80.1 108.28,80.14 125.38,80.2 129.9,80.3 130.7,80.3 131.5,80.3 132.3,80.3 133.1,80.3 133.9,80.3 92.5,80.6 121.84,80.6 106.68,80.64 109.68,80.64 150.16,80.64 110.7,80.7 135.1,80.7 135.9,80.7 136.7,80.7 137.5,80.7 138.3,80.7 139.1,80.7 139.9,80.7 140.7,80.7 141.5,80.7 142.3,80.7 143.1,80.7 143.9,80.7 144.7,80.7 145.5,80.7 146.3,80.7 147.1,80.7 147.9,80.7 148.7,80.7 113.96,80.72 126.18,80.74 115.84,80.9 103.3,81 128.08,81 129.6,81 130.9,81 131.9,81 133.1,81 134.3,81 127.1,81.02 91.7,81.1 128.82,81.18 108.28,81.24 121.22,81.22 110.7,81.5 130.2,81.7 131.3,81.7 132.4,81.7 133.5,81.7 134.7,81.7 135.8,81.7 137.1,81.7 138.2,81.7 139.3,81.7 140.4,81.7 141.5,81.7 142.6,81.7 143.9,81.7 145,81.7 146.1,81.7 147.2,81.7 148.3,81.7 149.4,81.7 150.16,81.74 104.86,81.76 92.5,81.8 106.68,81.84 109.68,81.84 120.64,81.9 129.18,81.92 114.1,81.94 111.92,82.08 103.3,82.2 91.7,82.3 108.28,82.44 129.6,82.8 130.7,82.8 131.9,82.8 133,82.8 134.1,82.8 135.3,82.8 136.4,82.8 137.7,82.8 138.8,82.8 139.9,82.8 141,82.8 142.1,82.8 143.2,82.8 144.5,82.8 145.6,82.8 146.7,82.8 147.8,82.8 148.9,82.8 150.16,82.84 92.5,82.9 104.86,82.96 112.68,83.02 106.64,83.16 109.64,83.16 125.7,83.2 91.7,83.4 103.3,83.4 101.1,83.5 110.9,83.6 120.66,83.62 124.639,83.701 108.24,83.76 93.8,83.9 130,83.94 131.14,83.98 132.24,83.98 133.5,84 134.6,84 135.8,84 136.9,84 138.2,84 139.3,84 140.4,84 141.5,84 142.6,84 143.7,84 145,84 146.1,84 147.2,84 148.3,84 149.4,84 124.131,84.082 104.86,84.16 150.16,84.14 92.5,84.2 106.64,84.26 109.64,84.26 103.3,84.5 91.7,84.7 101.1,84.7 108.24,84.86 130.44,84.92 93.8,85 150.16,85.24 104.86,85.26 131.54,85.26 132.76,85.26 133.86,85.26 92.5,85.3 135.3,85.3 136.5,85.3 137.6,85.3 138.9,85.3 140,85.3 141.1,85.3 142.2,85.3 143.3,85.3 144.4,85.3 145.7,85.3 146.8,85.3 147.9,85.3 149,85.3 117.28,85.42 115.02,85.44 120.6,85.44 106.64,85.46 109.64,85.46 103.3,85.7 91.7,85.8 120.9,85.8 108.24,86.06 93.8,86.1 150.16,86.34 92.5,86.4 106.08,86.78 114.9,86.82 112.6,86.84 91.7,86.9 129.8,86.9 132.5,86.9 133.6,86.9 134.7,86.9 135.88,86.9 137.2,86.9 138.3,86.9 139.6,86.9 140.7,86.9 142.9,86.9 144,86.9 145.1,86.9 146.1,86.9 147.2,86.9 148.3,86.9 149.4,86.9 131.56,86.92 101.1,87 122.8,87 124,87 125.3,87 126.7,87 128,87 93.8,87.2 103.4,87.2 150.16,87.44 92.5,87.5 91.7,88 145.5,88.06 146.6,88.06 147.7,88.06 148.8,88.06 101.1,88.2 105.1,88.26 93.8,88.3 150.16,88.54 92.5,88.6 91.7,89.1 146.08,89.28 147.18,89.28 148.28,89.28 149.38,89.28 93.8,89.4 92.5,89.7 150.16,89.78 91.7,90.2 93.8,90.5 145.94,90.52 147.04,90.52 148.14,90.52 149.24,90.52 92.5,90.8 150.16,90.88 91.5,91.7 92.6,91.7 93.8,91.7 94.9,91.7 96.2,91.7 97.3,91.7 98.4,91.7 99.5,91.7 100.6,91.7 101.7,91.7 103,91.7 104.1,91.7 105.2,91.7 106.3,91.7 107.4,91.7 108.6,91.7 109.9,91.7 111,91.7 112.1,91.7 113.2,91.7 114.4,91.7 115.5,91.7 116.8,91.7 117.9,91.7 119,91.7 120.1,91.7 121.2,91.7 122.3,91.7 123.6,91.7 124.7,91.7 125.8,91.7 126.9,91.7 128,91.7 129.3,91.7 130.6,91.7 131.7,91.7 132.8,91.7 133.9,91.7 135.1,91.7 136.2,91.7 137.5,91.7 138.6,91.7 139.7,91.7 140.8,91.7 141.9,91.7 143,91.7 144.3,91.7 145.4,91.7 146.5,91.7 147.6,91.7 148.7,91.7 150.16,91.98 92,92.5 93.1,92.5 94.3,92.5 95.4,92.5 96.7,92.5 97.8,92.5 98.9,92.5 100,92.5 101.1,92.5 102.2,92.5 103.5,92.5 104.6,92.5 105.7,92.5 106.8,92.5 107.9,92.5 109.1,92.5 110.4,92.5 111.5,92.5 112.6,92.5 113.7,92.5 114.9,92.5 116,92.5 117.3,92.5 118.4,92.5 119.5,92.5 120.6,92.5 121.7,92.5 122.8,92.5 124.1,92.5 125.2,92.5 126.3,92.5 127.4,92.5 128.5,92.5 129.8,92.5 131.1,92.5 132.2,92.5 133.3,92.5 134.4,92.5 135.6,92.5 136.7,92.5 138,92.5 139.1,92.5 140.2,92.5 141.3,92.5 142.4,92.5 143.5,92.5 144.8,92.5 145.9,92.5 147,92.5 148.1,92.5 149.2,92.5
NetC6_1: C6.1 C7.1 L1.2 U4.41 | length 7.9
  Top Layer w0.254: v1@117.568,74.768 117.704,74.632 U4.41@118.498,74.632
  Bottom Layer w0.254: L1.2@113.4,75.1 L1.2@113.5,75.2
  Bottom Layer w0.5: L1.2@113.5,75.2 117.06,75.2 117.48,74.78 118.135,74.78 C7.1@118.235,74.88
  Bottom Layer w0.7: C6.1@111.6,75.1 L1.2@113.4,75.1
  other v1: 117.5,74.82
NetC8_1: C8.1 U4.39 X1.2 | length 9.3
  Top Layer w0.254: X1.2@112.155,79.756 113.888,79.756 118.024,75.62 U4.39@118.26,75.62 ; X1.2@112.655,79.732 112.655,81.19 C8.1@112.665,81.2
NetC9_1: C9.1 U4.40 X1.1 | length 9
  Top Layer w0.254: X1.1@112.155,78.232 114.819,78.232 117.889,75.162 U4.40@118.6,75.162 ; X1.1@112.655,78.232 112.665,78.222 C9.1@112.665,77
NetC15_1: C15.1 C18.2 L3.1 U4.24 | length 2.5
  Top Layer w0.3: C15.1@127,79.998 C15.1@127.002,80
  Top Layer w0.625: 126.563,77.899 127,77.899 C18.2@127,78.998 ; C15.1@127,79.998 C18.2@127,78.998 ; C18.2@127.002,79 C18.2@127,78.998
NetC17_1: C17.1 C20.1 C24.2 C27.1 L4.1 L6.1 | length 5.5
  Top Layer w0.625: C17.1@132.462,76.6 C17.1@132.462,76.6
  Top Layer w0.7: L6.1@130.3,74.32 C24.2@130.3,75.5 ; C27.1@130.3,76.64 C24.2@130.3,75.5 ; L4.1@132.44,75.5 C24.2@130.3,75.5 ; L4.1@132.461,75.521 C17.1@132.462,76.6
NetC17_2: C17.2 C21.2 L4.2 L5.1 | length 2.8
  Top Layer w0.625: L4.2@133.659,75.5 L4.2@133.659,75.56
  Top Layer w0.7: L4.2@133.659,75.56 133.66,75.561 C17.2@133.66,76.58 ; L4.2@133.999,75.5 L5.1@135.7,75.5
NetC19_1: C19.1 C22.2 L7.2 | length 1.9
  Top Layer w0.7: C19.1@139.28,75.5 140.18,75.5 L7.2@141.181,75.5
NetC19_2: C19.2 L5.2 | length 1
  Top Layer w0.7: L5.2@136.979,75.5 C19.2@137.98,75.5
NetC24_1: C24.1 C35.1 L8.1 U4.21 | length 4
  Top Layer w0.25: U4.21@125.296,75.132 126.57,75.132 126.97,75.532 L8.1@127,75.502
  Top Layer w0.6: C24.1@129.101,75.499 C24.1@129.102,75.5
  Top Layer w0.7: L8.1@127,75.499 C24.1@129.101,75.499
NetC26_1: C26.1 C36.2 X2.1 | length 2.6
  Top Layer w0.2: X2.1@124.195,84.878 X2.1@124.385,84.878 ; C26.1@125.597,84.878 C26.1@125.619,84.9
  Top Layer w0.3: X2.1@124.385,84.878 C26.1@125.597,84.878 ; C26.1@125.619,84.9 C36.2@126.8,84.9
NetC27_2: C27.2 C35.2 L3.2 U4.23 | length 2.2
  Top Layer w0.25: L3.2@126.858,76.7 L3.2@126.9,76.7
  Top Layer w0.625: L3.2@126.9,76.7 L3.2@126.901,76.701 ; C27.2@129.101,76.701 C27.2@129.102,76.7
  Top Layer w0.7: L3.2@126.901,76.701 C27.2@129.101,76.701
NetC28_1: C28.1 J4.1 L7.1 | length 5.6
  Top Layer w0.7: L7.1@142.54,75.5 J4.1@148.1,75.5
NetC30_2: C30.2 L6.2 L8.2 U4.20 | length 3.9
  Top Layer w0.25: U4.20@125.296,74.632 126.568,74.632 126.899,74.301 L8.2@127,74.301
  Top Layer w0.625: L6.2@129.101,74.301 L6.2@129.102,74.3
  Top Layer w0.7: L8.2@127,74.301 L6.2@129.101,74.301
NetC31_1: C31.1 SB15.2 X2.3 | length 2.7
  Top Layer w0.254: C31.1@121.718,83.773 C31.1@121.773,83.828
  Top Layer w0.3: C31.1@121.773,83.828 X2.3@123.035,83.828
  Top Layer w0.4: SB15.2@123,82.5 123,83.793 X2.3@123.035,83.828
NetC36_1: C36.1 R100.2 | length 1.2
  Top Layer w0.3: R100.2@128,83.75 C36.1@128,84.898
  Top Layer w0.4: C36.1@127.998,84.9 C36.1@128,84.898
NetC37_2: C37.2 L9.1 X2.2 | length 5.3
  Top Layer w0.4: C37.2@122.898,86 L9.1@127,86
  Top Layer w0.625: C37.2@122.898,86 122.898,85.015 X2.2@123.035,84.878
  other v1: 123.242,84.717 122.734,85.098
NetL2_2: L2.2 U4.47 | length 3.2
  Top Layer w0.2: v1(117.5,70.5) 117.5,70.883 118.279,71.662 U4.47@118.6,71.662
  Bottom Layer w0.2: L2.2@116.652,69.7 116.652,70.002 116.85,70.2 117.1,70.2 117.4,70.5 v1(117.5,70.5)
NetR1_2: R1.2 SB11.1 | length 1
  Top Layer w0.5: SB11.1@130.525,69.469 131.369,69.469 R1.2@131.5,69.6
NetR100_1: R100.1 R101.1 SB13.2 | length 3.8
  Top Layer w0.2: SB13.2@124.5,82.5 SB13.2@124.6,82.6
  Top Layer w0.3: SB13.2@124.5,82.5 126.45,82.5 R101.1@126.8,82.85 R100.1@128,82.85
NetSB11_2: SB11.2 U4.19 | length 7.1
  Top Layer w0.15: U4.19@125.296,74.132 125.811,74.132 127.02,72.923 v1(127.02,72.46)
  Top Layer w0.2: v1(129.36,69.8) v1@129.369,69.8
  Top Layer w0.3: v1@129.369,69.8 SB11.2@129.7,69.469
  Bottom Layer w0.2: v1@127.02,72.48 126.96,72.42 126.96,71.74 128.9,69.8 v1(129.36,69.8)
NetSB13_1: SB13.1 U4.26 | length 4.5
  Top Layer w0.2: U4.26@124.158,77.282 124.158,80.558 124.5,80.9 SB13.1@124.5,81.6
NetSB15_1: SB15.1 U4.27 | length 4.7
  Top Layer w0.2: SB15.1@123,81.6 123,81.16 123.73,80.43 123.73,77.354 U4.27@123.658,77.282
